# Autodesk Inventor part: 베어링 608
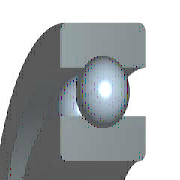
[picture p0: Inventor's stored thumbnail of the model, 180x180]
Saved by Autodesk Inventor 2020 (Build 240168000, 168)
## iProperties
Created: 2012-02
Part Number: 베어링 608
Material: 강철, 연강
Description: 깊은 그루브 볼 베어링
Document SubType Name: Modeling
Standard: KS B 2023
Designer: mduedu
Standards Organization: KS
Language: ko-KR
Size Designation: 608 - 8 x 22 x 7
Categories: <MemberInstance><Categories><Category DisplayName="샤프트 부품" InternalName="7f7aeb1f-a693-4053-b835-cee3144e0d98" Mnemonic="SHFT"><Category DisplayName="베어링" Inter
Density: 7.86 g/cm^3
Mass: 12.1605 g
Surface Area: 20.0754 cm^2
Volume: 1.54714 cm^3
Appearance: 노란색
IsCustomPart: 1
Author: mduedu
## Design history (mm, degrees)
sketch "스케치" dims "d0" = 3.64 (= -0.26 x WD + 0.26 x BD)
  geometry: L1 (1.68, 7.5)-(5.32, 7.5); L2 (3.5, 7.5)-(3.5, 5.68); L3 (3.5, 7.5)-(3.5, 9.32); L4 (2.148, 6.282)-(0, 6.282); L5 (0, 4)-(7, 4); L6 (2.148, 8.718)-(0, 8.718); L7 (0, 11)-(7, 11); L8 (7, 4)-(7, 6.282); L9 (4.852, 6.282)-(7, 6.282); L10 (4.852, 8.718)-(7, 8.718); L11 (7, 11)-(7, 8.718); L12 (-1.4, 0)-(8.4, 0) reference; L13 (0, -0.3)-(0, 5.3) reference
  constraints: 22 end point, 4 point on line, 2 collinear, 2 perpendicular, 2 symmetric about line, 1 midpoint, 1 parallel, 14 other
  dimensions: "d9" = 8 diameter of L5 L12 (= WD); "d11" = 22 diameter of L7 L12 (= BD); "d12" = 7 distance between parallel lines of L8 L13 (= KB); "d13" = 12.564 diameter of L9 L12 (= 0.326 x BD + 0.674 x WD)
revolve "본체" stored, may be unused: angle "d6" = 90 deg
revolve "볼" stored, may be unused: angle "d7" = 90 deg
pattern_circular "IDS_ARRAYBALL[SIMPL:T]" dims angle "d3" = 360 deg
body "Solid1"
fillet "모깎기1" dims "d1" = 0.3 (= KRS)
other parameters: "WD" = 8 [user parameter; used in 5 equation terms], "BD" = 22 [user parameter; used in 5 equation terms], "KB" = 7 [user parameter; used in 1 equation term], "KRS" = 0.3 [user parameter; used in 1 equation term], "d4" = 0, "d5" = 0, "d8" = 0, "d14" = 0, "d15" = 0, "BBA" = 0 [user parameter], "BC0" = 1370000 [user parameter], "BC" = 3250000 [user parameter], "BR" = 11 (= 0.5 x BD) [user parameter], "WR" = 4 (= 0.5 x WD) [user parameter]
